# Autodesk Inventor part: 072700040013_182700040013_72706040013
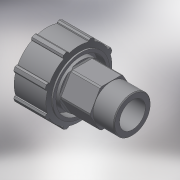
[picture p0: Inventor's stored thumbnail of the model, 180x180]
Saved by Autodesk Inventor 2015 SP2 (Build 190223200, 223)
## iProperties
Created: 2017-04
Part Number: 072700040013_182700040013_72706040013
Material: Generic
Description: PLASSON BRASS THREADED ADAPTOR 40-1.1/4"
Document SubType Name: Modeling
Designer: KIM
Density: 1 g/cm^3
Appearance: Default
Author: KIM
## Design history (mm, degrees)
derived "07270.ipt"
feature "Solid1::07270.ipt"
tag "TaggingFeature1"
body "Solid1"
other parameters: "d1" = 41.91, "d3" = 21, "d7" = 82, "d8" = 65.6, "d12" = 29.337, "d13" = 33.528, "d15" = 61.5, "d17" = 36, "d18" = 21, "d19" = 25.2, "d40" = 42, "d41" = 48.3, "d42" = 135 deg, "d43" = 100 deg, "d44" = 33.12, "d45" = 58.425, "d46" = 76.26, "d47" = 35 deg, "d48" = 17.5 deg, "d50" = 0, "d52" = 360 deg, "d54" = 1.64, "d57" = 1.64, "d61" = 0, "d62" = 0.8382, "d65" = 1.2573, "R_" = 41.91, "E_" = 82, "l_2" = 21, "Wrench" = 42
